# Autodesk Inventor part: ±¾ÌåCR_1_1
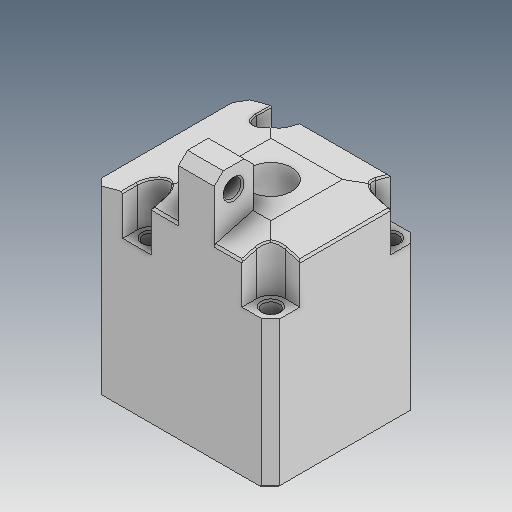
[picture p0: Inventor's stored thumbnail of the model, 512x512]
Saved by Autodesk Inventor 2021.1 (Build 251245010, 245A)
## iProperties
Created: 2019-04
Part Number: ±¾ÌåCR_1_1
Material: Ogólny
Document SubType Name: Modeling
Designer: user
Density: 1 g/cm^3
Appearance: Domyślna
Author: user
Revision Number: ÈÎºÎ
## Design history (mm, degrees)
feature "ÊäÈë1"
feature "ÊäÈë2"
node "Bryła1"
node "Bryła2"
